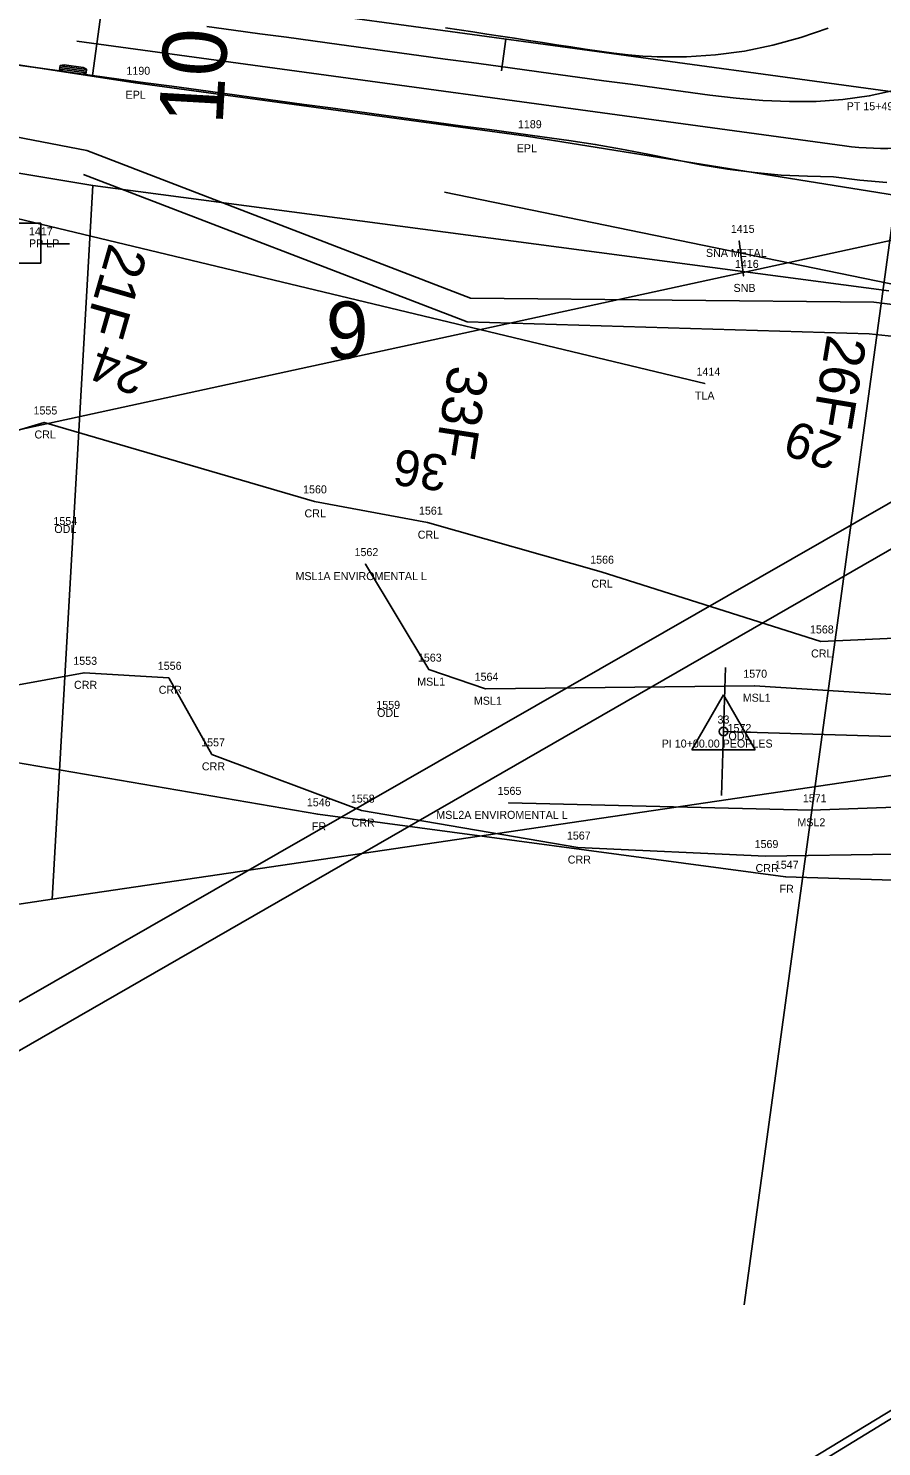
# Model space of a CAD drawing. Extents: x 1812113 to 1819860, y 1177290 to 1181185.
# Drawn here: x 1813531.1 to 1813637.8, y 1178588.3 to 1178765.6 of the extents above; entities that cross this region are included whole.
import ezdxf

# ---------------------------------------------------------------- set-up
doc = ezdxf.new("R2010")
doc.units = 0
for name, color, linetype in [('RD_EX_BldgApp', 7, 'Continuous'), ('RD_EX_BldgApp_txCode', 7, 'Continuous'), ('RD_EX_DV_Prop', 7, 'Continuous'), ('RD_EX_DV_TX_Prop', 7, 'Continuous'), ('RD_EX_Fence_Other', 7, 'Continuous'), ('RD_EX_Fence_Other_txCode', 7, 'Continuous'), ('RD_EX_H2O', 7, 'Continuous'), ('RD_EX_H2O_txCode', 7, 'Continuous'), ('RD_EX_Misc', 7, 'Continuous'), ('RD_EX_Misc_txCode', 7, 'Continuous'), ('RD_EX_Road', 7, 'Continuous'), ('RD_EX_Road_txCode', 7, 'Continuous'), ('RD_EX_RW', 7, 'Continuous'), ('RD_EX_UT', 7, 'Continuous'), ('RD_EX_UT_txCode', 7, 'Continuous'), ('RD_EX_VEG', 7, 'Continuous'), ('RD_EX_VEG_txCode', 7, 'Continuous'), ('RD_HC_CL', 7, 'Continuous'), ('RD_HC_Data', 7, 'Continuous'), ('RD_HC_Data_Tic', 7, 'Continuous'), ('RD_HC_TX_StaOther', 7, 'Continuous'), ('RD_HC_txCode', 7, 'Continuous'), ('RD_PD_CstnLmt', 7, 'Continuous'), ('RD_PD_DR_ErosCtrl', 7, 'Continuous'), ('RD_PD_PatLn1', 7, 'Continuous'), ('RD_Sketch5', 7, 'Continuous'), ('RD_Sketch9', 7, 'Continuous'), ('RD_SMD_Locator', 7, 'Continuous')]:
    doc.layers.add(name, color=color, linetype=linetype)

msp = doc.modelspace()

# ---------------------------------------------------------------- linework, layer by layer
at = {"layer": 'RD_EX_BldgApp'}
msp.add_line((1813619.98, 1178739.01), (1813620.52, 1178734.63), dxfattribs=at)
at = {"layer": 'RD_EX_DV_Prop'}
for p, q in [((1813534.09, 1178656.72), (1813539.17, 1178745.92)), ((1813739.05, 1178686.93), (1813534.09, 1178656.72)), ((1813396.08, 1178636.38), (1813534.09, 1178656.72))]:
    msp.add_line(p, q, dxfattribs=at)
at = {"layer": 'RD_EX_Fence_Other'}
for points in [[(1813495.44, 1178671.73), (1813524.97, 1178674.61), (1813567.3, 1178667.34), (1813625.77, 1178659.53), (1813676.75, 1178657.94), (1813689.16, 1178653.47)], [(1813689.16, 1178653.47), (1813706.15, 1178633.63), (1813541.42, 1178533.61)]]:
    msp.add_lwpolyline(points, dxfattribs=at)
at = {"layer": 'RD_EX_H2O'}
for points in [[(1813499.62, 1178706.37), (1813533.11, 1178716.31), (1813566.87, 1178706.45), (1813581.02, 1178703.79), (1813602.73, 1178697.66), (1813630.18, 1178688.94), (1813658.74, 1178690.22), (1813683.52, 1178690.56), (1813733.77, 1178695.63), (1813767.86, 1178725.16), (1813778.94, 1178729.95)], [(1813494.93, 1178677.14), (1813538.08, 1178685.02), (1813548.67, 1178684.4), (1813554.06, 1178674.83), (1813572.78, 1178667.8), (1813599.8, 1178663.18), (1813623.26, 1178662.12), (1813655.35, 1178662.6), (1813687.65, 1178668.53), (1813720.68, 1178667.78), (1813740.16, 1178669.89), (1813749.02, 1178672.08), (1813765.42, 1178660.89)]]:
    msp.add_lwpolyline(points, dxfattribs=at)
at = {"layer": 'RD_EX_Misc'}
for points in [[(1813405.71, 1178572.74), (1813779.17, 1178786.7), (1813799.35, 1179222.21)], [(1813408.47, 1178567.92), (1813786.33, 1178785.29), (1813804.76, 1179221.83)], [(1813573.26, 1178698.61), (1813581.18, 1178685.42), (1813588.27, 1178683.03), (1813621.87, 1178683.41), (1813652.09, 1178681.47), (1813685.62, 1178688.18), (1813723.85, 1178690.46), (1813735.91, 1178692.91), (1813768.22, 1178723.13), (1813784.54, 1178734.4), (1813800.79, 1178738.46), (1813839.24, 1178736.87), (1813863.9, 1178734.39), (1813884.49, 1178732.56), (1813903.28, 1178733.23)], [(1813591.15, 1178668.77), (1813628.98, 1178667.84), (1813655.76, 1178668.83), (1813686.95, 1178670.41), (1813726.51, 1178669.36), (1813738.94, 1178670.71), (1813788.68, 1178718.19), (1813806.25, 1178725.66), (1813819.18, 1178726.19), (1813847.08, 1178721.31), (1813860.38, 1178717.65), (1813871.97, 1178724.25), (1813883.92, 1178723.48), (1813902.67, 1178722.42)]]:
    msp.add_lwpolyline(points, dxfattribs=at)
at = {"layer": 'RD_EX_Road'}
msp.add_lwpolyline([(1813732.94, 1178707.95), (1813689.88, 1178731.75), (1813641.71, 1178744.36), (1813593.37, 1178752.09), (1813544.49, 1178758.77), (1813495.45, 1178766.29), (1813446.8, 1178774.66), (1813426.54, 1178777.95), (1813403.21, 1178782.55), (1813398.65, 1178783.84), (1813350.68, 1178796.09), (1813343.23, 1178797.92), (1813318.7, 1178804.23), (1813303.26, 1178808.85), (1813256.8, 1178823.17), (1813209.81, 1178838.91), (1813163.27, 1178855.57)], dxfattribs=at)
at = {"layer": 'RD_EX_RW'}
for q in [(1813409.98, 1178767.65), (1813638.67, 1178732.75)]:
    msp.add_line((1813539.17, 1178745.92), q, dxfattribs=at)
at = {"layer": 'RD_EX_UT'}
for p, q in [((1813532.69, 1178741.21), (1813527.69, 1178741.21)), ((1813532.69, 1178736.21), (1813532.69, 1178741.21)), ((1813532.62, 1178738.65), (1813536.26, 1178738.65)), ((1813527.69, 1178736.21), (1813532.69, 1178736.21))]:
    msp.add_line(p, q, dxfattribs=at)
msp.add_lwpolyline([(1813817.45, 1178777.9), (1813490.2, 1178706.76), (1813294.33, 1178669.42)], dxfattribs=at)
at = {"layer": 'RD_EX_VEG'}
for points in [[(1813615.69, 1178721.17), (1813497.56, 1178749.53), (1813481.72, 1178712.39)], [(1813569.58, 1178500.76), (1813635.35, 1178535.15), (1813737.8, 1178606.06), (1813775.9, 1178641.25), (1813752.75, 1178672.45), (1813690.46, 1178652.62), (1813708.11, 1178634.09), (1813540.71, 1178531.72)]]:
    msp.add_lwpolyline(points, dxfattribs=at)
at = {"layer": 'RD_HC_CL'}
for p, q in [((1813641.28, 1178757.34), (1813538.22, 1178771.42)), ((1813618, 1178677.68), (1813650.02, 1178676.71))]:
    msp.add_line(p, q, dxfattribs=at)
at = {"layer": 'RD_HC_Data'}
for p, q in [((1813641.28, 1178757.34), (1813620.6, 1178606.01)), ((1813614.03, 1178675.39), (1813618, 1178682.27)), ((1813618, 1178682.27), (1813621.97, 1178675.39)), ((1813614.03, 1178675.39), (1813621.97, 1178675.39))]:
    msp.add_line(p, q, dxfattribs=at)
msp.add_circle((1813618, 1178677.68), 0.529, dxfattribs=at)
at = {"layer": 'RD_HC_Data_Tic'}
for p, q in [((1813590.81, 1178764.23), (1813590.26, 1178760.27)), ((1813618, 1178677.68), (1813618.24, 1178685.67)), ((1813618, 1178677.68), (1813617.75, 1178669.68))]:
    msp.add_line(p, q, dxfattribs=at)
at = {"layer": 'RD_PD_CstnLmt'}
for p, q in [((1813538.44, 1178750.29), (1813429.25, 1178771.59)), ((1813538.44, 1178750.29), (1813586.38, 1178731.86)), ((1813586.38, 1178731.86), (1813636.78, 1178731.34)), ((1813636.78, 1178731.34), (1813681.37, 1178725.65))]:
    msp.add_line(p, q, dxfattribs=at)
at = {"layer": 'RD_PD_DR_ErosCtrl'}
for p, q in [((1813585.98, 1178728.89), (1813538.03, 1178747.32)), ((1813636.23, 1178727.38), (1813585.98, 1178728.89)), ((1813680.31, 1178722.84), (1813636.23, 1178727.38))]:
    msp.add_line(p, q, dxfattribs=at)
at = {"layer": 'RD_PD_PatLn1'}
msp.add_line((1813646.37, 1178732.12), (1813583.13, 1178745.1), dxfattribs=at)
at = {"layer": 'RD_Sketch5'}
for p, q in [((1813539.14, 1178759.69), (1813540.22, 1178767.61)), ((1813503.67, 1178764.53), (1813539.14, 1178759.69)), ((1813633.11, 1178750.88), (1813537.2, 1178763.99)), ((1813538.34, 1178760.01), (1813535.04, 1178760.46)), ((1813538.37, 1178760.21), (1813535.07, 1178760.66)), ((1813538.4, 1178760.42), (1813535.1, 1178760.87))]:
    msp.add_line(p, q, dxfattribs=at)
for points in [[(1813553.45, 1178765.81), (1813556.76, 1178765.35), (1813560.07, 1178764.9), (1813563.37, 1178764.45), (1813566.68, 1178764), (1813569.99, 1178763.55), (1813573.29, 1178763.09), (1813576.6, 1178762.64), (1813579.91, 1178762.19), (1813583.22, 1178761.74), (1813586.52, 1178761.29), (1813589.83, 1178760.83), (1813593.14, 1178760.38), (1813596.44, 1178759.93), (1813599.75, 1178759.48), (1813603.06, 1178759.03), (1813606.37, 1178758.58), (1813609.67, 1178758.12), (1813612.98, 1178757.67), (1813616.29, 1178757.23), (1813619.6, 1178756.85), (1813622.93, 1178756.56), (1813626.26, 1178756.41), (1813629.6, 1178756.43), (1813632.93, 1178756.66), (1813636.23, 1178757.12), (1813639.45, 1178757.84)], [(1813528.5, 1178761.14), (1813532.04, 1178760.66), (1813535.59, 1178760.17), (1813539.14, 1178759.69), (1813539.14, 1178759.69), (1813539.14, 1178759.69), (1813542.45, 1178759.24), (1813545.75, 1178758.78), (1813549.06, 1178758.33), (1813552.37, 1178757.88), (1813555.67, 1178757.43), (1813558.98, 1178756.98), (1813562.29, 1178756.52), (1813565.6, 1178756.07), (1813568.9, 1178755.62), (1813572.21, 1178755.17), (1813575.52, 1178754.72), (1813578.83, 1178754.26), (1813582.13, 1178753.81), (1813585.44, 1178753.36), (1813588.75, 1178752.91), (1813592.05, 1178752.46), (1813595.36, 1178752), (1813598.67, 1178751.55), (1813601.97, 1178751.06), (1813605.26, 1178750.46), (1813608.55, 1178749.83), (1813611.85, 1178749.16), (1813615.17, 1178748.53), (1813618.51, 1178747.98), (1813621.87, 1178747.54), (1813625.22, 1178747.24), (1813628.52, 1178747.08), (1813631.74, 1178747.03), (1813635.05, 1178746.58), (1813638.4, 1178746.3)]]:
    msp.add_lwpolyline(points, dxfattribs=at)
msp.add_lwpolyline([(1813538.4, 1178760.47), (1813538.33, 1178759.96), (1813537.85, 1178759.86), (1813535.47, 1178760.19), (1813535.03, 1178760.41), (1813535.1, 1178760.92), (1813535.59, 1178761.01), (1813537.96, 1178760.69)], close=True, dxfattribs=at)
msp.add_arc((1813637.85, 1178785.56), 35, 262.2191, 356.7565, dxfattribs=at)
at = {"layer": 'RD_Sketch9'}
for points in [[(1813609.01, 1178762.04), (1813607.92, 1178762.1), (1813606.1, 1178762.25), (1813604.29, 1178762.46), (1813602.49, 1178762.72), (1813600.7, 1178762.99), (1813598.91, 1178763.26), (1813597.14, 1178763.53), (1813595.38, 1178763.8), (1813593.63, 1178764.06), (1813591.88, 1178764.33), (1813590.14, 1178764.6), (1813588.41, 1178764.86), (1813586.68, 1178765.12), (1813584.96, 1178765.38), (1813583.25, 1178765.64)], [(1813631.1, 1178765.6), (1813627.67, 1178764.41), (1813624.17, 1178763.46), (1813620.61, 1178762.73), (1813617.01, 1178762.25), (1813613.38, 1178762.01), (1813609.73, 1178762.01), (1813609.01, 1178762.04)]]:
    msp.add_lwpolyline(points, dxfattribs=at)
at = {"layer": 'RD_SMD_Locator'}
for centre in [(1813544.49, 1178758.77), (1813593.37, 1178752.09), (1813619.98, 1178739.01), (1813620.52, 1178734.63), (1813615.69, 1178721.17), (1813533.11, 1178716.31), (1813566.87, 1178706.45), (1813535.61, 1178703.5), (1813581.02, 1178703.79), (1813573.26, 1178698.61), (1813602.73, 1178697.66), (1813630.18, 1178688.94), (1813538.08, 1178685.02), (1813548.67, 1178684.4), (1813581.18, 1178685.42), (1813588.27, 1178683.03), (1813621.87, 1178683.41), (1813575.96, 1178680.52), (1813618, 1178677.68), (1813619.86, 1178677.62), (1813554.06, 1178674.83), (1813591.15, 1178668.77), (1813567.3, 1178667.34), (1813572.78, 1178667.8), (1813628.98, 1178667.84), (1813599.8, 1178663.18), (1813623.26, 1178662.12), (1813625.77, 1178659.53)]:
    msp.add_circle(centre, 0.001, dxfattribs=at)

# ---------------------------------------------------------------- texts
at = {"layer": 'RD_EX_BldgApp_txCode'}
for s, p in [('1415', (1813618.92, 1178740.01)), ('SNA METAL', (1813615.81, 1178737.01)), ('1416', (1813619.43, 1178735.63)), ('SNB', (1813619.26, 1178732.63))]:
    msp.add_text(s, height=1, dxfattribs=at).set_placement(p)
at = {"layer": 'RD_EX_DV_TX_Prop'}
msp.add_text('9', height=7.14, dxfattribs=at).set_placement((1813568.31, 1178724.29))
at = {"layer": 'RD_EX_Fence_Other_txCode'}
for s, p in [('1546', (1813565.93, 1178668.34)), ('FR', (1813566.55, 1178665.34)), ('1547', (1813624.42, 1178660.53)), ('FR', (1813625.01, 1178657.53))]:
    msp.add_text(s, height=1, dxfattribs=at).set_placement(p)
at = {"layer": 'RD_EX_H2O_txCode'}
for s, p in [('1555', (1813531.77, 1178717.31)), ('CRL', (1813531.89, 1178714.31)), ('1560', (1813565.46, 1178707.45)), ('CRL', (1813565.64, 1178704.45)), ('1561', (1813579.94, 1178704.79)), ('1554', (1813534.26, 1178703.5)), ('ODL', (1813534.37, 1178702.5)), ('CRL', (1813579.79, 1178701.79)), ('1566', (1813601.34, 1178698.66)), ('CRL', (1813601.5, 1178695.66)), ('1568', (1813628.81, 1178689.94)), ('CRL', (1813628.95, 1178686.94)), ('1553', (1813536.74, 1178686.02)), ('1556', (1813547.3, 1178685.4)), ('CRR', (1813536.83, 1178683.02)), ('CRR', (1813547.42, 1178682.4)), ('1559', (1813574.61, 1178680.52)), ('ODL', (1813574.71, 1178679.52)), ('1572', (1813618.51, 1178677.62)), ('ODL', (1813618.62, 1178676.62)), ('1557', (1813552.72, 1178675.83)), ('CRR', (1813552.81, 1178672.83)), ('1558', (1813571.43, 1178668.8)), ('CRR', (1813571.52, 1178665.8)), ('1567', (1813598.43, 1178664.18)), ('1569', (1813621.89, 1178663.12)), ('CRR', (1813598.54, 1178661.18)), ('CRR', (1813622.01, 1178660.12))]:
    msp.add_text(s, height=1, dxfattribs=at).set_placement(p)
at = {"layer": 'RD_EX_Misc_txCode'}
for s, p in [('1562', (1813571.89, 1178699.61)), ('MSL1A ENVIROMENTAL L', (1813564.51, 1178696.61)), ('1563', (1813579.81, 1178686.42)), ('MSL1', (1813579.72, 1178683.42)), ('1564', (1813586.9, 1178684.03)), ('1570', (1813620.48, 1178684.41)), ('MSL1', (1813620.41, 1178681.41)), ('MSL1', (1813586.81, 1178681.03)), ('1565', (1813589.77, 1178669.77)), ('1571', (1813627.92, 1178668.84)), ('MSL2A ENVIROMENTAL L', (1813582.11, 1178666.77)), ('MSL2', (1813627.24, 1178665.84))]:
    msp.add_text(s, height=1, dxfattribs=at).set_placement(p)
at = {"layer": 'RD_EX_Road_txCode'}
for s, p in [('1190', (1813543.38, 1178759.77)), ('EPL', (1813543.28, 1178756.77)), ('1189', (1813592.31, 1178753.09)), ('EPL', (1813592.16, 1178750.09))]:
    msp.add_text(s, height=1, dxfattribs=at).set_placement(p)
at = {"layer": 'RD_EX_UT_txCode'}
for s, p in [('1417', (1813531.2, 1178739.7)), ('PP LP', (1813531.2, 1178738.2))]:
    msp.add_text(s, height=1, dxfattribs=at).set_placement(p)
at = {"layer": 'RD_EX_VEG_txCode'}
for s, p in [('1414', (1813614.63, 1178722.17)), ('TLA', (1813614.43, 1178719.17))]:
    msp.add_text(s, height=1, dxfattribs=at).set_placement(p)
at = {"layer": 'RD_HC_TX_StaOther'}
msp.add_text('10', height=8, rotation=86.7565, dxfattribs=at).set_placement((1813555.4, 1178753.44))
at = {"layer": 'RD_HC_txCode'}
for s, p in [('PT 15+49.06 RD S-41', (1813633.4, 1178755.34)), ('33', (1813617.26, 1178678.68)), ('PI 10+00.00 PEOPLES', (1813610.28, 1178675.68))]:
    msp.add_text(s, height=1, dxfattribs=at).set_placement(p)
at = {"layer": 'RD_PD_CstnLmt'}
for s, rotation, p in [('21F', 254.0378, (1813541.25, 1178738.88)), ('26F', 260.5629, (1813630.98, 1178727.43)), ('33F', 261.1616, (1813583.72, 1178723.6))]:
    msp.add_text(s, height=5, rotation=rotation, dxfattribs=at).set_placement(p)
at = {"layer": 'RD_PD_DR_ErosCtrl'}
for s, rotation, p in [('24', 159.8413, (1813546.3, 1178723.75)), ('29', 161.0986, (1813633.02, 1178714.48)), ('36', 172.0559, (1813583.76, 1178712.1))]:
    msp.add_text(s, height=4.5, rotation=rotation, dxfattribs=at).set_placement(p)

doc.saveas('drawing.dxf')
